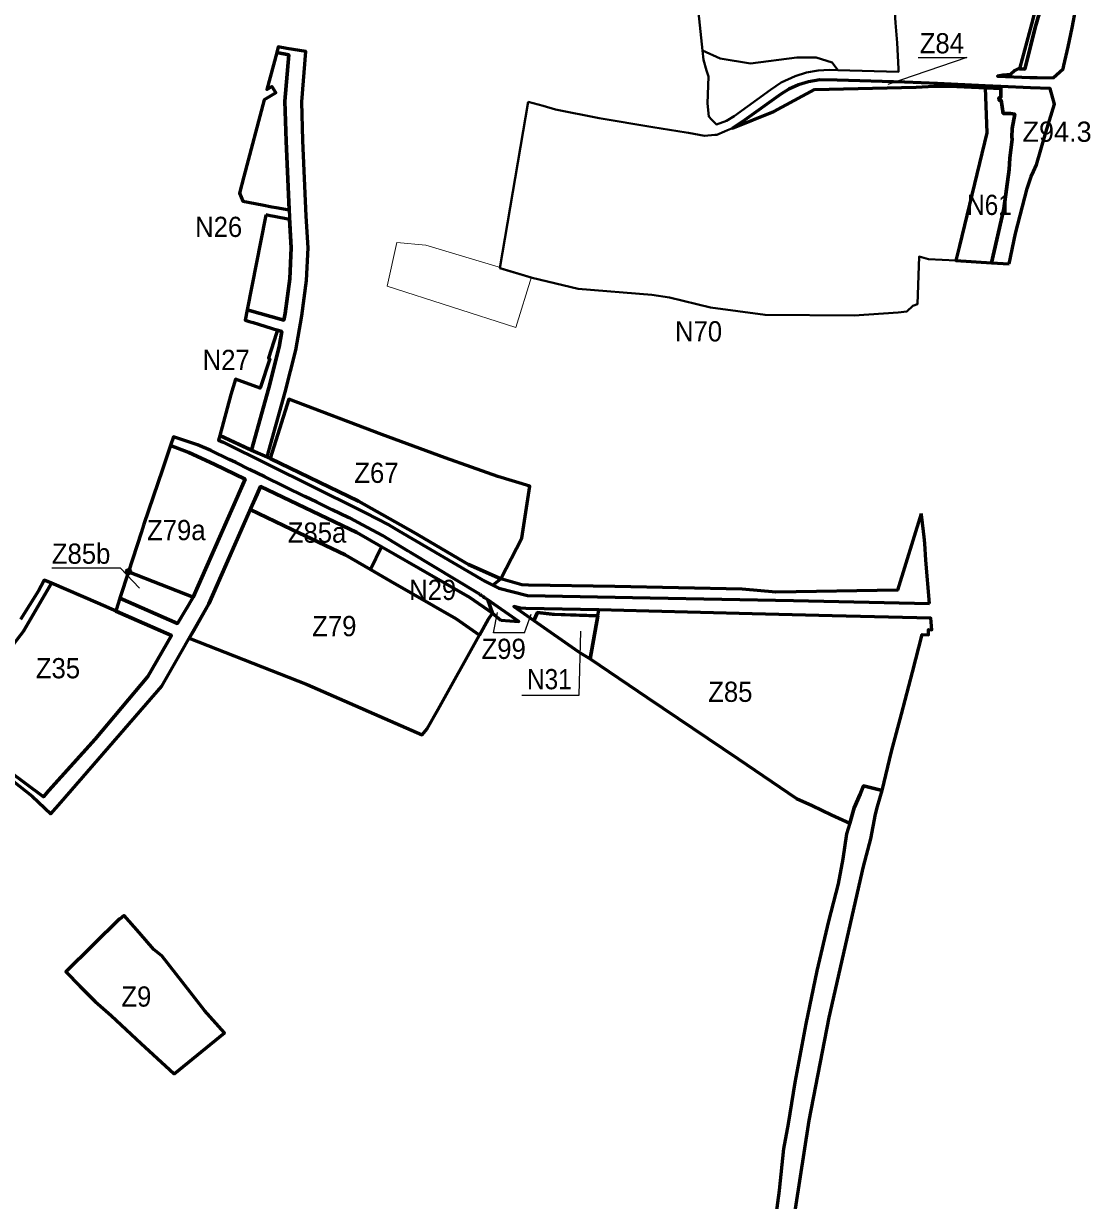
# Model space of a CAD drawing. Extents: x -650277 to -643422, y -1073980 to -1066720.
# Drawn here: x -646242 to -644975, y -1072093 to -1070696 of the extents above; entities that cross this region are included whole.
import ezdxf

# ---------------------------------------------------------------- set-up
doc = ezdxf.new("R2010")
doc.units = 0
doc.header["$LTSCALE"] = 9.6
doc.header["$PDMODE"] = 32
doc.header["$PDSIZE"] = 4.8
for name, color, linetype, lineweight in [('1', 7, 'Continuous', 60), ('11', 7, 'Continuous', 60), ('15', 7, 'Continuous', 60), ('18', 7, 'Continuous', 60), ('2', 7, 'Continuous', 40), ('20', 7, 'Continuous', 60), ('24', 7, 'Continuous', 60), ('40', 7, 'Continuous', 60), ('45', 7, 'Continuous', 60), ('59', 7, 'Continuous', 25), ('60', 7, 'Continuous', 60), ('63', 7, 'Continuous', 25)]:
    doc.layers.add(name, color=color, linetype=linetype, lineweight=lineweight)

msp = doc.modelspace()

# ---------------------------------------------------------------- linework, layer by layer
at = {"layer": '1'}
msp.add_lwpolyline([(-646102.04, -1071906.4), (-646068.317, -1071937.555), (-646062.91, -1071942.55), (-646002.93, -1071893.984), (-646026.64, -1071867.44), (-646043.49, -1071845.87), (-646077.32, -1071802.59), (-646087, -1071795), (-646104.5, -1071774.86), (-646122.16, -1071754.78), (-646127.12, -1071759.15), (-646127.84, -1071758.53), (-646191.57, -1071821.44), (-646174.69, -1071838.69), (-646156.59, -1071856.53), (-646137.74, -1071873.31)], close=True, dxfattribs=at)
at = {"layer": '11'}
msp.add_lwpolyline([(-646066.165, -1071422.155), (-646153.5, -1071383.85), (-646208.577, -1071360.044), (-646241.68, -1071416.887), (-646258.487, -1071439.265), (-646275.615, -1071460.886), (-646289.976, -1071477.514), (-646330.914, -1071521.11), (-646324, -1071535), (-646217.978, -1071613.552), (-646211.407, -1071606.247), (-646156.471, -1071545.166), (-646094.063, -1071471.007)], close=True, dxfattribs=at)
at = {"layer": '15'}
for points in [[(-645039.574, -1070675.065), (-645045.493, -1070696.321), (-645059.308, -1070747.712), (-645059.403, -1070749.195), (-645053.21, -1070749.75), (-645052.4, -1070746.427), (-645046.63, -1070722.77), (-645041, -1070700.44), (-645033.53, -1070674.55)], [(-645955.342, -1071233.725), (-645973.324, -1071224.925), (-645989.7, -1071216.91), (-645997.62, -1071213.03), (-646019.41, -1071202.36), (-646035.06, -1071195.87), (-646063.59, -1071186.33), (-646067.097, -1071196.699), (-646045.462, -1071204.917), (-646015.387, -1071218.854), (-645978.403, -1071236.481), (-646040.084, -1071376.813), (-646058.719, -1071407.796), (-646127.301, -1071378.036), (-646131.79, -1071391.83), (-646132.229, -1071393.179), (-646066.165, -1071422.155), (-646094.063, -1071471.007), (-646156.471, -1071545.166), (-646211.407, -1071606.247), (-646217.978, -1071613.552)], [(-645701.44, -1071372.25), (-645782.32, -1071323.5), (-645784.92, -1071321.93), (-645815.65, -1071303.41), (-645839.37, -1071290.6), (-645854.1, -1071282.93), (-645856.26, -1071281.91), (-645875.48, -1071272.81), (-645893.41, -1071264.04), (-645907.62, -1071257.08), (-645955.342, -1071233.725)], [(-646223.928, -1071620.168), (-646209.322, -1071634.004), (-646197.398, -1071620.579), (-646077.593, -1071482.499), (-646021.674, -1071384.575), (-645964.396, -1071254.314), (-645960.34, -1071245.09)], [(-645960.34, -1071245.09), (-645846, -1071300), (-645712, -1071377)], [(-646241.68, -1071416.887), (-646208.577, -1071360.044), (-646217.049, -1071356.382), (-646220.61, -1071363.16), (-646223.77, -1071369.24), (-646245.1, -1071403.04)], [(-645712, -1071377), (-645685.098, -1071395.824), (-645690.677, -1071379.721)], [(-646217.978, -1071613.552), (-646324, -1071535)], [(-646261.46, -1071589.38), (-646231.43, -1071613.06), (-646223.928, -1071620.168)]]:
    msp.add_lwpolyline(points, dxfattribs=at)
for points in [[(-645911.345, -1070788.463), (-645906.373, -1070728.716), (-645929.077, -1070725.068), (-645939.27, -1070723.43), (-645940.955, -1070729.799), (-645926.784, -1070732.812), (-645931.369, -1070787.913), (-645930.036, -1070835.367), (-645926.084, -1070925.481), (-645923.919, -1070961.855), (-645925.626, -1070998.754), (-645931.24, -1071039.686), (-645932.635, -1071047.688), (-645976.17, -1071035.39), (-645978.58, -1071047.68), (-645973.77, -1071049.17), (-645968.97, -1071050.66), (-645940.25, -1071059.59), (-645934.978, -1071061.119), (-645938.15, -1071079.311), (-645950.283, -1071128.057), (-645970.966, -1071202.169), (-645952.419, -1071210.117), (-645930.943, -1071133.161), (-645918.57, -1071083.449), (-645911.474, -1071042.764), (-645905.69, -1071000.578), (-645903.891, -1070961.723), (-645906.11, -1070924.449), (-645910.048, -1070834.649)], [(-645694.15, -1071357.83), (-645684.785, -1071362.539), (-645674.947, -1071355.071), (-645713.428, -1071337.765), (-645778.69, -1071299.362), (-645844.079, -1071262.487), (-645948.761, -1071211.885), (-645967, -1071204), (-646008.714, -1071184.746), (-646010.14, -1071190.08), (-646004.65, -1071192.55), (-645951.118, -1071219.11), (-645843.45, -1071272.53), (-645835.76, -1071276.35), (-645808.13, -1071290.78), (-645795.97, -1071297.93), (-645694.15, -1071357.83)]]:
    msp.add_lwpolyline(points, close=True, dxfattribs=at)
msp.add_arc((-645538.107, -1071148.434), 277.076, 233.87926, 236.5888, dxfattribs=at)
at = {"layer": '18'}
for points in [[(-645678.86, -1071233.58), (-645741.09, -1071211.36), (-645816.47, -1071183.63), (-645926.81, -1071141.595), (-645948.761, -1071211.885)], [(-645948.761, -1071211.885), (-645844.079, -1071262.487), (-645778.69, -1071299.362), (-645713.428, -1071337.765), (-645674.947, -1071355.071)], [(-645674.947, -1071355.071), (-645650.09, -1071306.433), (-645640.737, -1071244.963), (-645678.86, -1071233.58)]]:
    msp.add_lwpolyline(points, dxfattribs=at)
at = {"layer": '2'}
for points in [[(-645442.836, -1070659.455), (-645426.34, -1070660.33), (-645209.41, -1070651.2), (-645206.7, -1070694.76), (-645204.66, -1070718.51), (-645203.13, -1070749.36), (-645202.96, -1070752.89), (-645275.236, -1070750.954), (-645282, -1070742), (-645301, -1070736), (-645324, -1070736), (-645379, -1070743), (-645415, -1070737), (-645435.711, -1070727.497)], [(-645275.236, -1070750.954), (-645285.11, -1070750.69), (-645298.41, -1070751.48), (-645312.2, -1070753.77), (-645325.82, -1070757.94), (-645342.41, -1070765.76), (-645354.98, -1070774.28), (-645398.04, -1070805.44), (-645407.37, -1070810.95), (-645419.18, -1070815.44), (-645424.969, -1070809.563), (-645428.39, -1070806.09), (-645430, -1070790.68), (-645428.73, -1070758.67), (-645430.84, -1070751.43), (-645434.53, -1070738.77), (-645435.711, -1070727.497), (-645415, -1070737), (-645379, -1070743), (-645324, -1070736), (-645301, -1070736), (-645282, -1070742)]]:
    msp.add_lwpolyline(points, close=True, dxfattribs=at)
for points in [[(-645100.268, -1070771.946), (-645143, -1070770), (-645161, -1070770), (-645182, -1070771), (-645303, -1070774), (-645351, -1070800), (-645400.05, -1070819.84), (-645406.09, -1070822.34), (-645409.52, -1070823.76), (-645418.67, -1070827.72), (-645421.09, -1070827.89), (-645433.49, -1070828.76), (-645452.31, -1070825.52), (-645455.184, -1070825.042)], [(-645130.749, -1070959.561), (-645098.438, -1070825.558), (-645100.268, -1070771.946)], [(-645642.52, -1070788.7), (-645676.292, -1070985.89), (-645637.94, -1070997.4), (-645583.18, -1071010.7), (-645495.87, -1071017.81)], [(-645455.184, -1070825.042), (-645494.82, -1070818.45), (-645558.3, -1070808), (-645610.25, -1070797.55), (-645625, -1070793.5), (-645642.52, -1070788.7)], [(-645495.87, -1071017.81), (-645475.01, -1071020.72), (-645426.38, -1071032.8), (-645361.54, -1071041.54), (-645255.93, -1071042.36), (-645203.66, -1071038.81), (-645193.24, -1071037.31), (-645186.18, -1071030.83), (-645180.72, -1071028.86), (-645178.73, -1070972.35), (-645167.47, -1070975.2), (-645134.973, -1070977.077), (-645134.973, -1070977.077), (-645130.749, -1070959.561)]]:
    msp.add_lwpolyline(points, dxfattribs=at)
at = {"layer": '2', "lineweight": 13}
msp.add_lwpolyline([(-645638.648, -1070996.51), (-645657.288, -1071056.48), (-645809.828, -1071007.55), (-645798.468, -1070955.63), (-645764.238, -1070958.82)], close=True, dxfattribs=at)
at = {"layer": '20'}
for points in [[(-645990.48, -1071263.958), (-645978.403, -1071236.481), (-646015.387, -1071218.854), (-646045.462, -1071204.917), (-646067.097, -1071196.699), (-646076.713, -1071225.138)], [(-646076.713, -1071225.138), (-646098.66, -1071290.03), (-646102.011, -1071300.326), (-646117.031, -1071346.48)], [(-646117.031, -1071346.48), (-646040.084, -1071376.813), (-645990.48, -1071263.958)]]:
    msp.add_lwpolyline(points, dxfattribs=at)
msp.add_lwpolyline([(-645972.423, -1071272.568), (-646021.674, -1071384.575), (-646039.658, -1071416.067), (-646044.948, -1071425.333), (-645905.027, -1071480.359), (-645768.62, -1071540.17), (-645762.54, -1071533.015), (-645749.631, -1071509.908), (-645700.38, -1071421.746), (-645728.054, -1071402.382), (-645806.036, -1071357.564), (-645829.706, -1071343.963), (-645859.986, -1071326.563), (-645923.023, -1071296.291), (-645972.422, -1071272.568)], close=True, dxfattribs=at)
msp.add_point((-646117.031, -1071346.48), dxfattribs=at)
at = {"layer": '24'}
msp.add_lwpolyline([(-645303, -1070774), (-645182, -1070771), (-645161, -1070770), (-645143, -1070770), (-645125.217, -1070770.81), (-645081.75, -1070772.79), (-645081.6, -1070770.362), (-645100.32, -1070769.5), (-645156.988, -1070766.884), (-645195.527, -1070765.319), (-645195.527, -1070765.319), (-645275.8, -1070762.66), (-645296.51, -1070762.52), (-645309.78, -1070764.88), (-645321.9, -1070768.47), (-645333.12, -1070773.33), (-645342.94, -1070779.31), (-645385.99, -1070810.35), (-645400.05, -1070819.84), (-645351, -1070800)], close=True, dxfattribs=at)
at = {"layer": '40'}
for points in [[(-645926.457, -1070916.969), (-645930.036, -1070835.367), (-645931.369, -1070787.913), (-645926.784, -1070732.812), (-645940.955, -1070729.799), (-645952.65, -1070773.98), (-645946.81, -1070770.47), (-645942.3, -1070777.96), (-645955.86, -1070786.21), (-645980.01, -1070877.28), (-645985.28, -1070897.13), (-645981.48, -1070906.35), (-645958.21, -1070910.84)], [(-645958.21, -1070910.84), (-645946.85, -1070913.03), (-645941.94, -1070913.98), (-645926.457, -1070916.969)], [(-645954.01, -1070922.8), (-645954.492, -1070925.251), (-645976.17, -1071035.39), (-645932.635, -1071047.688), (-645931.24, -1071039.686), (-645925.626, -1070998.754), (-645923.919, -1070961.855), (-645925.908, -1070928.435)], [(-645925.908, -1070928.435), (-645944.08, -1070924.79), (-645948.99, -1070923.81), (-645954.01, -1070922.8)]]:
    msp.add_lwpolyline(points, dxfattribs=at)
for points in [[(-645970.966, -1071202.169), (-645950.283, -1071128.057), (-645938.15, -1071079.311), (-645934.978, -1071061.119), (-645940.25, -1071059.59), (-645941.45, -1071063.3), (-645950.96, -1071092.8), (-645949.21, -1071093.62), (-645960.66, -1071128.71), (-645990.14, -1071117.76), (-645995.74, -1071136.22), (-646008.714, -1071184.746)], [(-645700.38, -1071421.746), (-645690.056, -1071403.266), (-645685.098, -1071395.824), (-645712, -1071377), (-645816.714, -1071316.828), (-645829.706, -1071343.963), (-645806.036, -1071357.564), (-645728.054, -1071402.382)], [(-645583.18, -1071441.3), (-645580.947, -1071442.658), (-645569.07, -1071449.88), (-645560.11, -1071398.7), (-645611.58, -1071397.14), (-645631.44, -1071394.9), (-645635.795, -1071404.403)]]:
    msp.add_lwpolyline(points, close=True, dxfattribs=at)
at = {"layer": '45'}
for points in [[(-645100.268, -1070771.946), (-645098.438, -1070825.558), (-645130.749, -1070959.561), (-645134.972, -1070977.077), (-645092.67, -1070979.52)], [(-645083.49, -1070786.92), (-645083.95, -1070783.89), (-645081.57, -1070783.53), (-645081.85, -1070781.59), (-645081.75, -1070772.79), (-645100.268, -1070771.946)], [(-645092.67, -1070979.52), (-645078.23, -1070915.65), (-645071.77, -1070868.73), (-645071.18, -1070855.63), (-645068.07, -1070832.72), (-645068.52, -1070830.52), (-645068.07, -1070820.37), (-645065.01, -1070803.22), (-645070.2, -1070802.33), (-645078.85, -1070802.46), (-645081.13, -1070786.56), (-645083.49, -1070786.92)]]:
    msp.add_lwpolyline(points, dxfattribs=at)
at = {"layer": '59'}
msp.add_lwpolyline([(-645180, -1070736), (-645122, -1070736), (-645216, -1070768)], dxfattribs=at)
at = {"layer": '60'}
for points in [[(-645033.53, -1070674.55), (-645041, -1070700.44), (-645046.63, -1070722.77), (-645052.4, -1070746.427), (-645053.21, -1070749.75), (-645060.46, -1070749.1), (-645065.17, -1070751.39), (-645070.3, -1070755.92), (-645079.38, -1070756.91), (-645085.58, -1070758.04), (-645047.39, -1070759.71), (-645038.44, -1070759.83), (-645019.57, -1070760.07), (-645007.68, -1070749.5), (-645006.739, -1070745.384), (-645001.71, -1070723.39), (-644997.14, -1070700.88), (-644992.6, -1070677.92)], [(-645071.99, -1070980.72), (-645064.39, -1070944.7), (-645050.47, -1070891.48), (-645045.74, -1070877.19), (-645043, -1070871.35), (-645039.25, -1070863.33), (-645028.25, -1070824.83), (-645018.18, -1070791.34), (-645023.25, -1070772.62), (-645046.46, -1070771.98), (-645081.6, -1070770.362), (-645081.75, -1070772.79), (-645081.85, -1070781.59), (-645081.57, -1070783.53)], [(-645081.57, -1070783.53), (-645083.95, -1070783.89), (-645083.49, -1070786.92), (-645081.13, -1070786.56), (-645078.85, -1070802.46), (-645070.2, -1070802.33)], [(-645070.2, -1070802.33), (-645065.01, -1070803.22), (-645068.07, -1070820.37)], [(-645068.07, -1070820.37), (-645068.52, -1070830.52), (-645068.07, -1070832.72), (-645071.18, -1070855.63), (-645071.77, -1070868.73), (-645078.23, -1070915.65)], [(-645078.23, -1070915.65), (-645092.67, -1070979.52), (-645071.99, -1070980.72)], [(-645176.14, -1071277.26), (-645204.341, -1071368.19), (-645348.55, -1071370.559), (-645388.619, -1071366.991), (-645539.738, -1071364.092), (-645642.431, -1071362.259), (-645650.28, -1071362.07), (-645674.947, -1071355.071), (-645684.785, -1071362.539), (-645677.58, -1071366.16), (-645643.56, -1071374.75), (-645497.84, -1071377.53), (-645327.76, -1071380.76), (-645166.34, -1071384.07)], [(-645166.34, -1071384.07), (-645170.91, -1071332.86), (-645172.03, -1071312.96), (-645172.85, -1071305.45), (-645175.4, -1071281.93), (-645175.67, -1071279.45), (-645176.14, -1071277.26)], [(-645222.48, -1071606.08), (-645244.81, -1071600.61), (-645248.786, -1071610.383), (-645255.662, -1071626.67)], [(-645339.904, -1072462.677), (-645347.551, -1072443.527), (-645347.677, -1072391.355), (-645346.62, -1072330.914), (-645343.458, -1072278.998), (-645339.908, -1072235.158), (-645335.367, -1072185.207), (-645325.498, -1072102.789), (-645309.01, -1071998.147), (-645285.617, -1071875.733), (-645244.798, -1071696.585), (-645235.793, -1071663.703), (-645230.436, -1071634.261), (-645227.905, -1071625.277), (-645222.48, -1071606.08)], [(-645255.662, -1071626.67), (-645261.094, -1071645.025), (-645264.841, -1071657.687), (-645269.077, -1071687.396), (-645274.868, -1071717.176), (-645286.175, -1071761.228), (-645300.076, -1071820.179), (-645313.153, -1071883.081)], [(-645313.153, -1071883.081), (-645326.343, -1071952.807), (-645334.118, -1072001.954), (-645339.455, -1072031.565), (-645344.819, -1072081.225), (-645351.358, -1072130.815), (-645361.317, -1072232.824), (-645364.435, -1072280.268), (-645366.951, -1072331.609), (-645370.624, -1072401.447), (-645372.228, -1072438.764)]]:
    msp.add_lwpolyline(points, dxfattribs=at)
for points in [[(-645303, -1070774), (-645182, -1070771), (-645161, -1070770), (-645143, -1070770), (-645125.217, -1070770.81), (-645081.75, -1070772.79), (-645081.6, -1070770.362), (-645100.32, -1070769.5), (-645156.988, -1070766.884), (-645195.527, -1070765.319), (-645195.527, -1070765.319), (-645275.8, -1070762.66), (-645296.51, -1070762.52), (-645309.78, -1070764.88), (-645321.9, -1070768.47), (-645333.12, -1070773.33), (-645342.94, -1070779.31), (-645385.99, -1070810.35), (-645400.05, -1070819.84), (-645351, -1070800)], [(-645816.714, -1071316.828), (-645846, -1071300), (-645960.34, -1071245.09), (-645964.396, -1071254.314), (-645972.422, -1071272.568), (-645972.422, -1071272.568), (-645923.023, -1071296.291), (-645859.986, -1071326.563), (-645829.705, -1071343.962)], [(-646045.393, -1071385.64), (-646040.084, -1071376.813), (-646117.031, -1071346.48), (-646127.301, -1071378.036), (-646058.719, -1071407.796)], [(-645675.177, -1071403.922), (-645675.177, -1071403.922), (-645653.742, -1071405.36), (-645690.677, -1071379.721), (-645685.098, -1071395.824)], [(-645614.201, -1071396.844), (-645560.11, -1071398.7), (-645558.872, -1071391.801), (-645558.9, -1071391.8), (-645645.368, -1071389.96), (-645651.93, -1071389.82), (-645659.6, -1071387.71), (-645647.727, -1071396.036), (-645635.795, -1071404.403), (-645631.44, -1071394.9)], [(-645560.11, -1071398.7), (-645569.07, -1071449.88), (-645501.37, -1071495.68), (-645393.34, -1071568.75), (-645324.17, -1071615.53), (-645324.17, -1071615.53), (-645305.78, -1071624.13), (-645282.54, -1071634.997), (-645261.094, -1071645.025), (-645255.662, -1071626.67), (-645248.786, -1071610.383), (-645244.81, -1071600.61), (-645222.48, -1071606.08), (-645222.48, -1071606.08), (-645211.27, -1071560.01), (-645199.61, -1071515.68), (-645186.67, -1071465.55), (-645175.06, -1071420.93), (-645167.58, -1071421.19), (-645167.37, -1071415.2), (-645163.56, -1071415.3), (-645164.76, -1071401.79), (-645281.92, -1071398.82), (-645376.87, -1071396.41), (-645499.65, -1071393.3), (-645558.9, -1071391.8), (-645645.368, -1071389.96), (-645651.93, -1071389.82), (-645659.6, -1071387.71), (-645647.727, -1071396.036), (-645635.795, -1071404.403), (-645631.44, -1071394.9), (-645614.201, -1071396.844)]]:
    msp.add_lwpolyline(points, close=True, dxfattribs=at)
at = {"layer": '63'}
msp.add_line((-645647, -1071419), (-645639, -1071397), dxfattribs=at)
for points in [[(-646208, -1071342), (-646127, -1071342), (-646104, -1071366)], [(-645647, -1071419), (-645684, -1071419), (-645679, -1071395)], [(-645650, -1071493), (-645582, -1071493), (-645580, -1071417)]]:
    msp.add_lwpolyline(points, dxfattribs=at)

# ---------------------------------------------------------------- texts
at = {"layer": '59', "width": 0.95}
for s, p in [('Z84', (-645178, -1070731)), ('N70', (-645468.436, -1071073.045))]:
    msp.add_text(s, height=24, dxfattribs=at).set_placement(p)
at = {"layer": '63'}
msp.add_text('Z94.3', height=24, dxfattribs=at).set_placement((-645056, -1070836))
for s, width, p in [('N61', 0.9, (-645121.693, -1070922.874)), ('N26', 0.95, (-646038, -1070949)), ('N27', 0.95, (-646029, -1071107)), ('Z67', 0.95, (-645849, -1071241)), ('Z79a', 0.95, (-646095, -1071309)), ('Z85a', 0.95, (-645928, -1071312)), ('Z85b', 0.95, (-646208, -1071337)), ('N29', 0.95, (-645784, -1071380)), ('Z79', 0.95, (-645899, -1071423)), ('Z99', 0.95, (-645698, -1071450)), ('Z35', 0.95, (-646227, -1071473)), ('N31', 0.9, (-645644, -1071486)), ('Z85', 0.95, (-645429, -1071501)), ('Z9', 0.95, (-646125.48, -1071862.818))]:
    msp.add_text(s, height=24, dxfattribs=dict(at, width=width)).set_placement(p)

doc.saveas('drawing.dxf')
